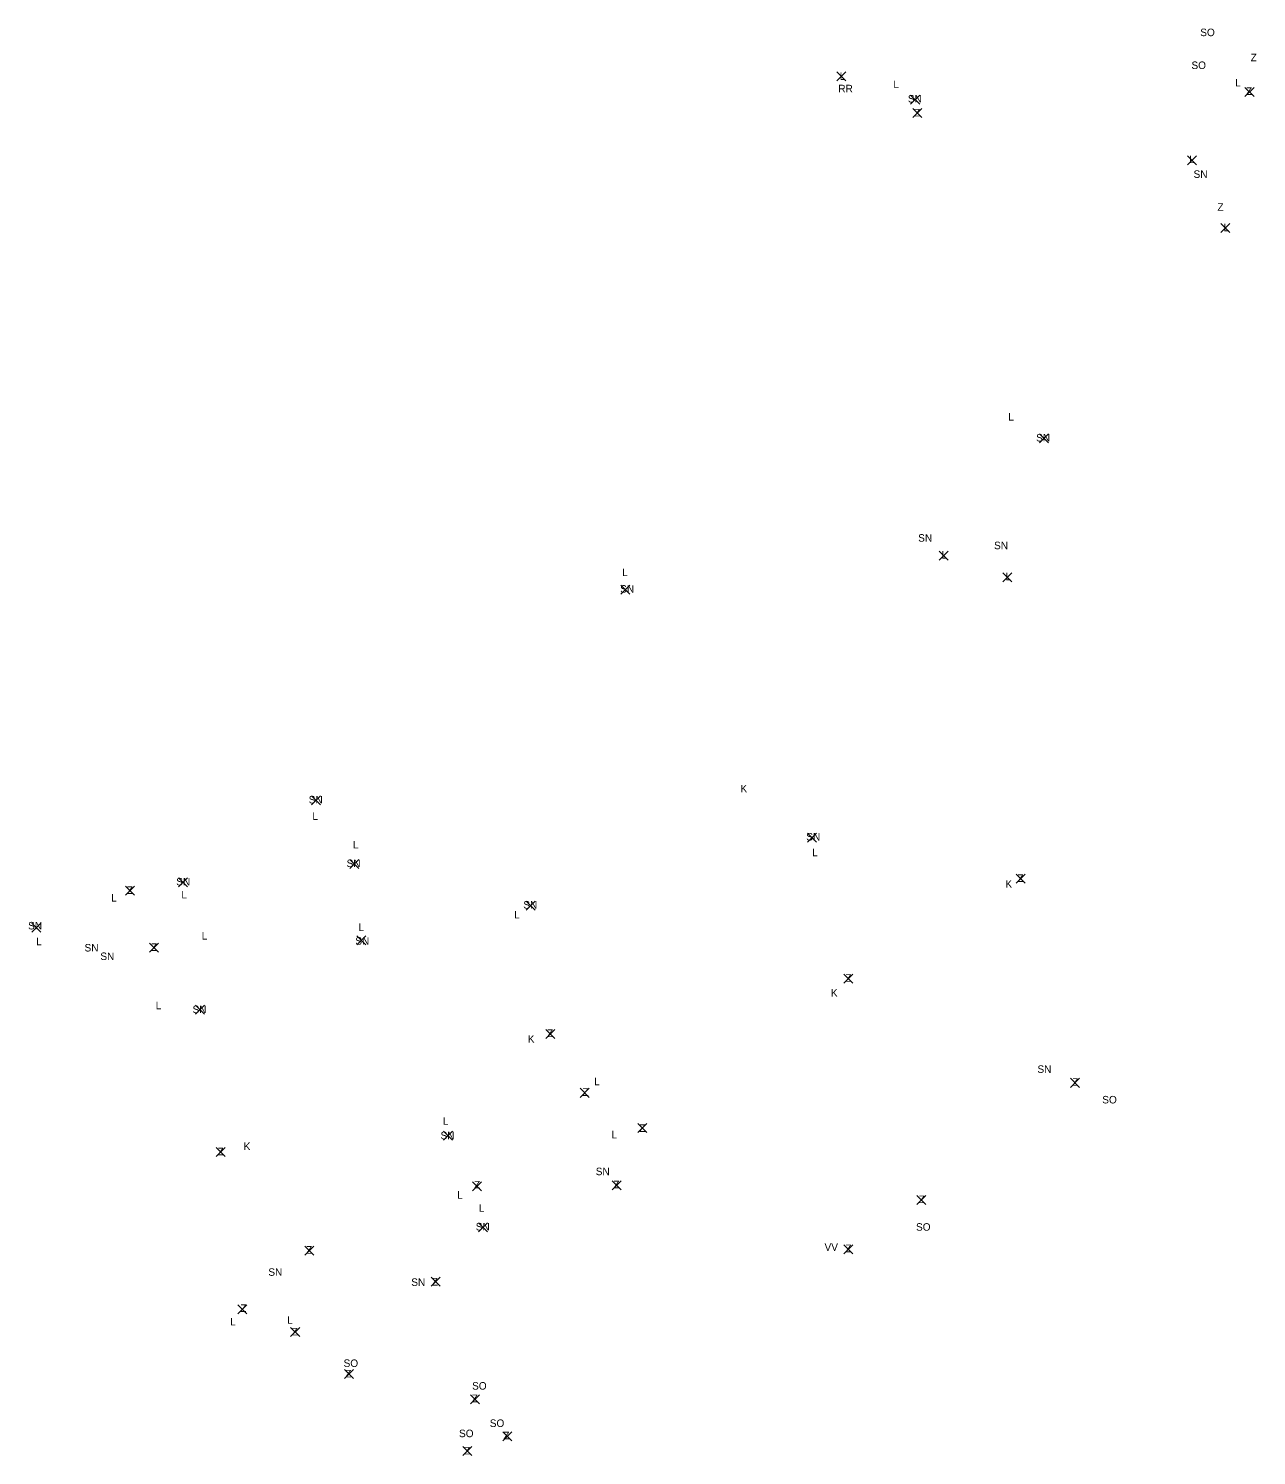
# Model space of a CAD drawing. Extents: x -444381 to -436234, y -1141793 to -1129925.
# Drawn here: x -444381 to -442748, y -1133753 to -1131856 of the extents above; entities that cross this region are included whole.
import ezdxf

# ---------------------------------------------------------------- set-up
doc = ezdxf.new("R2010")
doc.units = 0
doc.layers.add('Vrstva 200', color=7, linetype='Continuous')
doc.layers.add('Vrstva 4', color=7, linetype='Continuous')

msp = doc.modelspace()

# ---------------------------------------------------------------- linework, layer by layer
at = {"layer": 'Vrstva 200'}
for p, q in [((-443306, -1131925.9), (-443294, -1131913.9)), ((-443306, -1131913.9), (-443294, -1131925.9)), ((-443207.9, -1131956.7), (-443195.9, -1131944.7)), ((-443207.9, -1131944.7), (-443195.9, -1131956.7)), ((-442763.3, -1131946.5), (-442751.3, -1131934.5)), ((-442763.3, -1131934.5), (-442751.3, -1131946.5)), ((-443204.9, -1131974.6), (-443192.9, -1131962.6)), ((-443204.9, -1131962.6), (-443192.9, -1131974.6)), ((-442839.9, -1132037.6), (-442827.9, -1132025.6)), ((-442839.9, -1132025.6), (-442827.9, -1132037.6)), ((-442795.5, -1132127.5), (-442783.5, -1132115.5)), ((-442795.5, -1132115.5), (-442783.5, -1132127.5)), ((-443036.4, -1132407.1), (-443024.4, -1132395.1)), ((-443036.4, -1132395.1), (-443024.4, -1132407.1)), ((-443170.1, -1132562.9), (-443158.1, -1132550.9)), ((-443170.1, -1132550.9), (-443158.1, -1132562.9)), ((-443085.3, -1132591.9), (-443073.3, -1132579.9)), ((-443085.3, -1132579.9), (-443073.3, -1132591.9)), ((-443593.4, -1132608.1), (-443581.4, -1132596.1)), ((-443593.4, -1132596.1), (-443581.4, -1132608.1)), ((-444004.5, -1132888.3), (-443992.5, -1132876.3)), ((-444004.5, -1132876.3), (-443992.5, -1132888.3)), ((-443345, -1132938), (-443333, -1132926)), ((-443345, -1132926), (-443333, -1132938)), ((-443345, -1132938), (-443333, -1132926)), ((-443345, -1132926), (-443333, -1132938)), ((-443953.9, -1132972.7), (-443941.9, -1132960.7)), ((-443953.9, -1132960.7), (-443941.9, -1132972.7)), ((-444181.6, -1132997.2), (-444169.6, -1132985.2)), ((-444181.6, -1132985.2), (-444169.6, -1132997.2)), ((-443067.7, -1132992.5), (-443055.7, -1132980.5)), ((-443067.7, -1132980.5), (-443055.7, -1132992.5)), ((-444252.1, -1133008.3), (-444240.1, -1132996.3)), ((-444252.1, -1132996.3), (-444240.1, -1133008.3)), ((-443719.4, -1133028.2), (-443707.4, -1133016.2)), ((-443719.4, -1133016.2), (-443707.4, -1133028.2)), ((-444376.5, -1133057.4), (-444364.5, -1133045.4)), ((-444376.5, -1133045.4), (-444364.5, -1133057.4)), ((-443944.4, -1133074.2), (-443932.4, -1133062.2)), ((-443944.4, -1133062.2), (-443932.4, -1133074.2)), ((-444220.1, -1133084.1), (-444208.1, -1133072.1)), ((-444220.1, -1133072.1), (-444208.1, -1133084.1)), ((-443296.6, -1133125.3), (-443284.6, -1133113.3)), ((-443296.6, -1133113.3), (-443284.6, -1133125.3)), ((-444159.1, -1133166.3), (-444147.1, -1133154.3)), ((-444159.1, -1133154.3), (-444147.1, -1133166.3)), ((-443693.2, -1133198.7), (-443681.2, -1133186.7)), ((-443693.2, -1133186.7), (-443681.2, -1133198.7)), ((-442995.4, -1133263.7), (-442983.4, -1133251.7)), ((-442995.4, -1133251.7), (-442983.4, -1133263.7)), ((-443647.4, -1133277), (-443635.4, -1133265)), ((-443647.4, -1133265), (-443635.4, -1133277)), ((-443570.9, -1133323.9), (-443558.9, -1133311.9)), ((-443570.9, -1133311.9), (-443558.9, -1133323.9)), ((-443829.1, -1133333.8), (-443817.1, -1133321.8)), ((-443829.1, -1133321.8), (-443817.1, -1133333.8)), ((-444131.3, -1133355.7), (-444119.3, -1133343.7)), ((-444131.3, -1133343.7), (-444119.3, -1133355.7)), ((-443790.7, -1133401.4), (-443778.7, -1133389.4)), ((-443790.7, -1133389.4), (-443778.7, -1133401.4)), ((-443604.7, -1133399.9), (-443592.7, -1133387.9)), ((-443604.7, -1133387.9), (-443592.7, -1133399.9)), ((-443199.6, -1133419.5), (-443187.6, -1133407.5)), ((-443199.6, -1133407.5), (-443187.6, -1133419.5)), ((-443782.5, -1133455.9), (-443770.5, -1133443.9)), ((-443782.5, -1133443.9), (-443770.5, -1133455.9)), ((-444013.7, -1133486.6), (-444001.7, -1133474.6)), ((-444013.7, -1133474.6), (-444001.7, -1133486.6)), ((-443296.7, -1133485), (-443284.7, -1133473)), ((-443296.7, -1133473), (-443284.7, -1133485)), ((-443845.5, -1133527.9), (-443833.5, -1133515.9)), ((-443845.5, -1133515.9), (-443833.5, -1133527.9)), ((-444102.7, -1133564.6), (-444090.7, -1133552.6)), ((-444102.7, -1133552.6), (-444090.7, -1133564.6)), ((-444032.4, -1133594.9), (-444020.4, -1133582.9)), ((-444032.4, -1133582.9), (-444020.4, -1133594.9)), ((-443960.9, -1133650.9), (-443948.9, -1133638.9)), ((-443960.9, -1133638.9), (-443948.9, -1133650.9)), ((-443793.2, -1133684.3), (-443781.2, -1133672.3)), ((-443793.2, -1133672.3), (-443781.2, -1133684.3)), ((-443750.4, -1133733.5), (-443738.4, -1133721.5)), ((-443750.4, -1133721.5), (-443738.4, -1133733.5)), ((-443803.3, -1133753), (-443791.3, -1133741)), ((-443803.3, -1133741), (-443791.3, -1133753))]:
    msp.add_line(p, q, dxfattribs=at)

# ---------------------------------------------------------------- texts
at = {"layer": 'Vrstva 4'}
for s, p in [('SO', (-442822.8, -1131866.4)), ('Z', (-442755.8, -1131899.8)), ('SO', (-442834.5, -1131910.1)), ('L', (-443302.3, -1131924.6)), ('L', (-443230.9, -1131935.5)), ('L', (-442776.3, -1131933.3)), ('RR', (-443304.1, -1131941.1)), ('SN', (-443211.6, -1131954.6)), ('Z', (-442762, -1131944.5)), ('Z', (-443203.3, -1131973.1)), ('L', (-442837.6, -1132035.2)), ('SN', (-442831.7, -1132054.8)), ('Z', (-442799.9, -1132098.5)), ('L', (-442791.7, -1132125.7)), ('L', (-443078.1, -1132377.5)), ('SN', (-443041.1, -1132405.2)), ('SN', (-443197.9, -1132538.4)), ('L', (-443167, -1132560.8)), ('SN', (-443097, -1132548.4)), ('L', (-443591.6, -1132584.2)), ('L', (-443081.9, -1132589.7)), ('SN', (-443594.2, -1132606.2)), ('SN', (-444008.4, -1132886.3)), ('K', (-443434.2, -1132871.6)), ('L', (-444003.5, -1132908.2)), ('SN', (-443346.7, -1132935.6)), ('L', (-443949.5, -1132946.1)), ('L', (-443338.9, -1132956.6)), ('SN', (-443958, -1132970.9)), ('SN', (-444184.6, -1132995.3)), ('K', (-443081.9, -1132998.4)), ('Z', (-443066, -1132990.7)), ('L', (-444271.2, -1133016.8)), ('Z', (-444250.3, -1133006.7)), ('L', (-444177.7, -1133012.5)), ('L', (-443735.3, -1133039.1)), ('SN', (-443723, -1133026.1)), ('SN', (-444381.6, -1133053.8)), ('L', (-443942.2, -1133055.9)), ('L', (-444370.9, -1133074.9)), ('L', (-444150.7, -1133067.4)), ('SN', (-443946.4, -1133074.1)), ('SN', (-444306.5, -1133083.1)), ('SN', (-444285.5, -1133094.5)), ('Z', (-444218.2, -1133082.4)), ('Z', (-443294.8, -1133123.4)), ('K', (-443314, -1133143.1)), ('L', (-444211.9, -1133160)), ('SN', (-444162.9, -1133165.1)), ('K', (-443717, -1133204.4)), ('Z', (-443691.5, -1133196.8)), ('SN', (-443039.3, -1133244.5)), ('L', (-443628.8, -1133260.9)), ('Z', (-442993.1, -1133261.6)), ('Z', (-443644.4, -1133275)), ('SO', (-442953.1, -1133285.1)), ('L', (-443830, -1133313.5)), ('Z', (-443568.7, -1133322.9)), ('SN', (-443833.1, -1133332.7)), ('L', (-443605.7, -1133331.5)), ('Z', (-444129.6, -1133353.9)), ('K', (-444094.9, -1133347)), ('SN', (-443626.7, -1133380.5)), ('Z', (-443788.4, -1133398)), ('Z', (-443603.2, -1133397.8)), ('L', (-443811, -1133411.7)), ('Z', (-443197.2, -1133417.5)), ('L', (-443782.2, -1133429.1)), ('SN', (-443786.3, -1133453.9)), ('SO', (-443200.8, -1133454.3)), ('Z', (-444011.9, -1133484.8)), ('VV', (-443322.4, -1133481.2)), ('Z', (-443294.8, -1133482.8)), ('SN', (-444062.1, -1133514.2)), ('SN', (-443872, -1133527.7)), ('Z', (-443844.8, -1133527.1)), ('Z', (-444099.4, -1133562.3)), ('L', (-444112.9, -1133580.2)), ('L', (-444037.1, -1133577.9)), ('Z', (-444031, -1133593.5)), ('SO', (-443962, -1133635.4)), ('Z', (-443959.8, -1133649.2)), ('SO', (-443791.1, -1133665.5)), ('Z', (-443791.5, -1133682.2)), ('SO', (-443767.6, -1133715.1)), ('SO', (-443808.5, -1133728.7)), ('Z', (-443749.4, -1133731.4)), ('Z', (-443801.8, -1133751.7))]:
    msp.add_text(s, height=10, dxfattribs=at).set_placement(p)

doc.saveas('drawing.dxf')
